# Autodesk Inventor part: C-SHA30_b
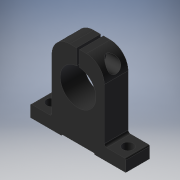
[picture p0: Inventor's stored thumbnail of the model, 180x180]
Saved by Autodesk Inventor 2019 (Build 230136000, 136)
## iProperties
Created: 2022-11
Part Number: C-SHA30_b
Material: Generic
Catalog Web Link: www.cadenas.de
Description: C-SHA_base-Economy Shaft Supports - T-Shaped/Slit
Vendor: MISUMI
Document SubType Name: Modeling
Designer: psAdmin
Manufacturer: MISUMI
Mass: 48.6779 g
Surface Area: 141.331 cm^2
Volume: 48.6779 cm^3
Density: 1 g/cm^3
Appearance: PSOLRGB-175-175-175
Category: PARTsolutions
Company: MISUMI
Title: C-SHA30
Author: Cadenas PARTsolutions
Comments: Economy Shaft Supports - T-Shaped/Slit
PSOL_IDENT_0: {$CADENAS_DATA/23d-libs/misumi/metric/02_shaft_supports/c_sha/c_sha_base.prj},160 {VTYP=3D},{NB=C-SH
PSOL_IDENT_1: A30_b},{LINA=C-SHA30},{NN=C-SHA_base},{DATE=04.10.2022 06:54:53},{GEOMDATE=23.04.2021 02:46:37},{VER
PSOL_IDENT_2: SION=},{LINEID=60},{WBVAR=},{WBNUMERIC=}  {NB=C-SHA30_b},{LINA=C-SHA30},{KT=DUMMY},{PN=C-SHA30},{TYP
PSOL_IDENT_3: E=C-SHA},{D=30},{H=42},{H1=70},{T=20},{L1=64},{DD=9.0},{E=21.0},{S=10},{R=15},{L=80},{B=28},{W=44},{
PSOL_IDENT_4: M=M6},{R2=2},{W2=2.5},{M3D=6},{M3D2=13.5},{M3D3=11},{M3D4=6.4},{LB=20}
NB: C-SHA30_b
NN: C-SHA_base
NT: Economy Shaft Supports - T-Shaped/Slit
NBSYN: $PN._b
LINA: C-SHA30
CATALOG: Misumi
PN: C-SHA30
D: 30
H: 42
H1: 70
T: 20
L1: 64
DD: 9
E: 21
S: 10
R: 15
L: 80
B: 28
W: 44
M: M6
SUPPLIER: MISUMI
ARTICLENO: C-SHA30_b
BOMINFO: C-SHA30
CREATOR: CADENAS GmbH
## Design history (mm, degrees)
sketch "_____1"
  geometry: L1 (-40, -33)-(-40, -42); L2 (-40, -42)-(-14, -42); L3 (-13, -41)-(13, -41); L4 (14, -42)-(40, -42); L5 (40, -42)-(40, -33); L6 (39, -32)-(24, -32); L7 (22, -30)-(22, 13); L8 (7, 28)-(-7, 28); L9 (-22, 13)-(-22, -30); L10 (-24, -32)-(-39, -32); A1 r 1 centre (-13, -42) between (-13, -41) and (-14, -42); A2 r 1 centre (13, -42) between (14, -42) and (13, -41); A3 r 1 centre (39, -33) between (40, -33) and (39, -32); A4 r 2 centre (24, -30) between (22, -30) and (24, -32); A5 r 15 centre (7, 13) between (22, 13) and (7, 28); A6 r 15 centre (-7, 13) between (-7, 28) and (-22, 13); A7 r 2 centre (-24, -30) between (-24, -32) and (-22, -30); A8 r 1 centre (-39, -33) between (-39, -32) and (-40, -33)
  constraints: 20 end point, 16 point on circle, 8 centre point
extrude "Extrusion1" join sketch "_____1" stored distance "d0" = 20; taper "d1" = 0 deg
sketch "_____2"
  geometry: L1 (1.25, 14.948)-(1.25, 70); L2 (1.25, 70)-(-1.25, 70); L3 (-1.25, 70)-(-1.25, 14.948); A1 r 15 centre (0, 0) between (-1.25, 14.948) and (1.25, 14.948)
  constraints: 6 end point, 2 point on circle, 1 centre point
extrude "Extrusion2" cut sketch "_____2" stored distance "d2" = 20; taper "d3" = 0 deg
sketch "_____3"
  geometry: C1 r 4.5 at (32, 0); 1 further point
  constraints: 1 centre point
extrude "Extrusion3" cut sketch "_____3" distance "d4" = 42; taper "d5" = 0 deg
sketch "_____4"
  geometry: C1 r 4.5 at (-32, 0); 1 further point
  constraints: 1 centre point
extrude "Extrusion4" cut sketch "_____4" distance "d6" = 42; taper "d7" = 0 deg
sketch "_____5"
  geometry: L1 (50, 21)-(-50, 21); L2 (0, 21)-(0, 24.2); L3 (0, 24.2)-(8.5, 24.2); L4 (8.5, 24.2)-(8.5, 26.5); L5 (8.5, 26.5)-(22, 26.5); L6 (22, 26.5)-(22, 21); L7 (22, 21)-(0, 21)
  constraints: 14 end point
revolve "Revolution1" sketch "_____5" stored, may be unused: angle "d8" = 360 deg
sketch "Sketch6"
  geometry: 1 further point
hole "Hole1" sketch "Sketch6" at (10, 6.052) diameter "d9" = 4.917; stored, may be unused: countersink angle "d13" = 90 deg, drill point angle "d15" = 0 deg; dims "d10" = 20.75, "d11" = 6, "d12" = 2, "d14" = 20.75
node "to_bolt_XY"
node "to_bolt_YZ"
node "to_bolt_ZX"
node "to_bolt_X"
node "to_bolt_Y"
node "to_bolt_Z"
node "to_bolt_Center"
body "Solid1"
other parameters: "d16" = 0
